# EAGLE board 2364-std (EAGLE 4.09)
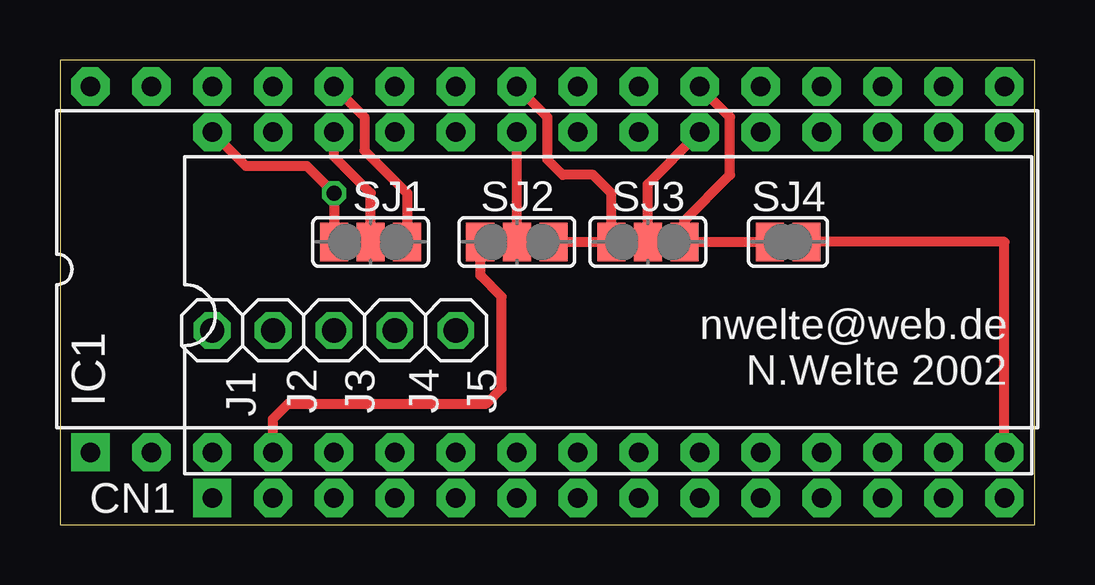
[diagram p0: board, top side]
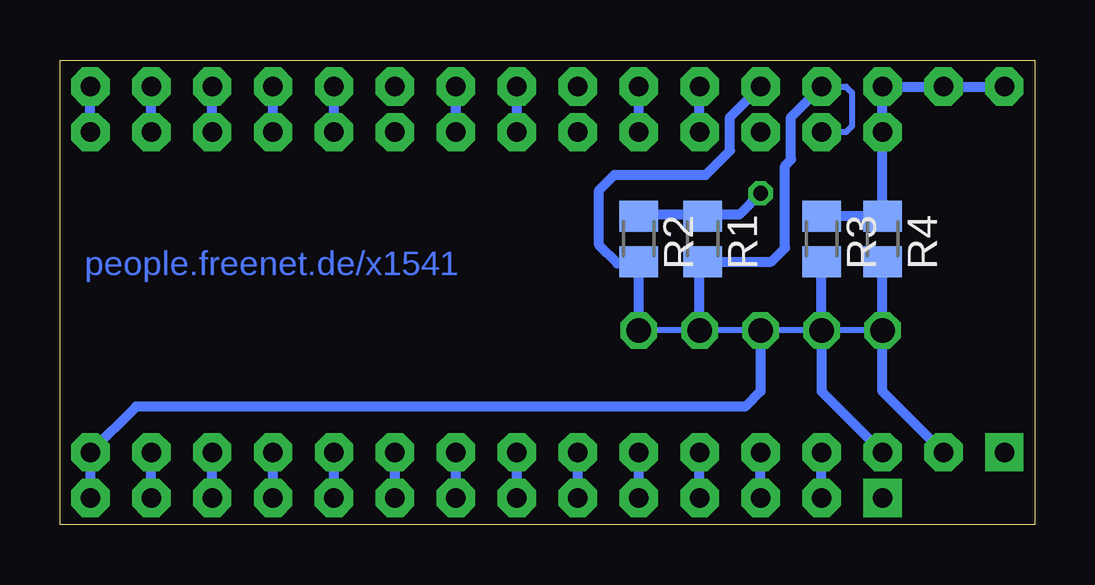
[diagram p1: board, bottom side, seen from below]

Size 40.63 x 19.36 mm. Coordinates in mm from the lower left corner, seen from the top.
Outline: 40.63,0 40.63,19.36 0,19.36 0,0 40.63,0
Copper layers used: Top, Bottom

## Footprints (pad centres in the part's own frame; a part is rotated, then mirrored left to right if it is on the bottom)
DIL28-6 = drill 0.813 pad 1.6 square: 1 -16.51,-7.62 | drill 0.813 pad 1.6 octagon: 2 -13.97,-7.62; 3 -11.43,-7.62; 4 -8.89,-7.62; 5 -6.35,-7.62; 6 -3.81,-7.62; 7 -1.27,-7.62; 8 1.27,-7.62; 9 3.81,-7.62; 10 6.35,-7.62; 11 8.89,-7.62; 12 11.43,-7.62; 13 13.97,-7.62; 14 16.51,-7.62; 15 16.51,7.62; 16 13.97,7.62; 17 11.43,7.62; 18 8.89,7.62; 19 6.35,7.62; 20 3.81,7.62; 21 1.27,7.62; 22 -1.27,7.62; 23 -3.81,7.62; 24 -6.35,7.62; 25 -8.89,7.62; 26 -11.43,7.62; 27 -13.97,7.62; 28 -16.51,7.62
DIL32-3 = drill 0.813 pad 1.6 square: 1 -19.05,-3.81 | drill 0.813 pad 1.6 octagon: 2 -16.51,-3.81; 3 -13.97,-3.81; 4 -11.43,-3.81; 5 -8.89,-3.81; 6 -6.35,-3.81; 7 -3.81,-3.81; 8 -1.27,-3.81; 9 1.27,-3.81; 10 3.81,-3.81; 11 6.35,-3.81; 12 8.89,-3.81; 13 11.43,-3.81; 14 13.97,-3.81; 15 16.51,-3.81; 16 19.05,-3.81; 17 19.05,11.43; 18 16.51,11.43; 19 13.97,11.43; 20 11.43,11.43; 21 8.89,11.43; 22 6.35,11.43; 23 3.81,11.43; 24 1.27,11.43; 25 -1.27,11.43; 26 -3.81,11.43; 27 -6.35,11.43; 28 -8.89,11.43; 29 -11.43,11.43; 30 -13.97,11.43; 31 -16.51,11.43; 32 -19.05,11.43
1X01 = drill 1.016 octagon: 1 0,0
M0805 = smd 1.3 x 1.6: 1 -0.95,0; 2 0.95,0
SJ_2 = smd 1.168 x 1.6: 1 -1.524,0; 2 0,0; 3 1.524,0
SJ = smd 1.168 x 1.6: 1 -0.762,0; 2 0.762,0

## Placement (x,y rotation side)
CN1  [DIL28-6]  22.85,8.72 0 top
IC1  AT29C010  [DIL32-3]  20.31,6.82 0 top
J1  [1X01]  8.88,8.09 90 top
J2  [1X01]  6.35,8.09 90 top
J3  [1X01]  11.43,8.09 90 top
J4  [1X01]  13.96,8.09 90 top
J5  [1X01]  16.5,8.09 90 top
R1  [M0805]  13.84,11.9 270 bottom
R2  [M0805]  16.5,11.9 270 bottom
R3  [M0805]  8.88,11.9 270 bottom
R4  [M0805]  6.35,11.9 270 bottom
SJ1  [SJ_2]  12.95,11.77 0 top
SJ2  [SJ_2]  19.04,11.77 0 top
SJ3  [SJ_2]  24.51,11.77 0 top
SJ4  [SJ]  30.35,11.77 0 top

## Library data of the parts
CN1 = memory-hitachi
IC1 = am29-memory
J1-J5 = pinhead
R1-R4 = rcl
SJ1-SJ4 = jumper

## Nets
A0: CN1.10 IC1.12
A1: CN1.9 IC1.11
A2: CN1.8 IC1.10
A3: CN1.7 IC1.9
A4: CN1.6 IC1.8
A5: CN1.5 IC1.7
A6: CN1.4 IC1.6
A7: CN1.3 IC1.5
A8: CN1.25 IC1.27
A9: CN1.24 IC1.26
A10: CN1.21 IC1.23
A11: CN1.20 IC1.25 SJ2.3 SJ3.1 SJ3.2
A12: CN1.2 CN1.23 IC1.4 SJ2.1 SJ2.2
A13: CN1.14 CN1.27 IC1.2 IC1.3 IC1.16 IC1.22 IC1.28 IC1.29 J1.1 J2.1 J3.1 J4.1 J5.1 R1.2 R2.2 R3.2 R4.2 SJ1.3 SJ3.3 SJ4.1 SJ4.2
D0: CN1.11 IC1.13
D1: CN1.12 IC1.14
D2: CN1.13 IC1.15
D3: CN1.15 IC1.17
D4: CN1.16 IC1.18
D5: CN1.17 IC1.19
D6: CN1.18 IC1.20
D7: CN1.19 IC1.21
OE: CN1.22 IC1.24
VCC: CN1.26 CN1.28 IC1.30 IC1.31 IC1.32 R1.1 R2.1 R3.1 R4.1 SJ1.1 SJ1.2

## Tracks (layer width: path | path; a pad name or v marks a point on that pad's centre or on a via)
A0
  Bottom 0.406: CN1.10 IC1.12
A1
  Bottom 0.406: CN1.9 IC1.11
A2
  Bottom 0.406: CN1.8 IC1.10
A3
  Bottom 0.406: CN1.7 IC1.9
A4
  Bottom 0.406: CN1.6 IC1.8
A5
  Bottom 0.406: CN1.5 IC1.7
A6
  Bottom 0.406: CN1.4 IC1.6
A7
  Bottom 0.406: CN1.3 IC1.5
A8
  Bottom 0.406: CN1.25 IC1.27
A9
  Bottom 0.406: CN1.24 IC1.26
A10
  Bottom 0.406: CN1.21 IC1.23
A11
  Top 0.254: SJ3.1 SJ3.2
  Top 0.406: SJ2.3 SJ3.1 22.98,13.8 22.22,14.57 20.95,14.57 20.31,15.2 20.31,16.98 IC1.25 | SJ3.2 24.51,14.19 CN1.20
A12
  Top 0.254: SJ2.1 SJ2.2
  Top 0.406: SJ2.1 17.52,10.38 18.41,9.49 18.41,5.68 17.77,5.04 9.52,5.04 8.88,4.41 IC1.4 | SJ2.2 CN1.23
  Bottom 0.406: CN1.2 IC1.4
A13
  Top 0.254: SJ4.1 SJ4.2
  Top 0.406: SJ1.3 14.47,13.8 12.7,15.58 12.7,16.98 IC1.28 | SJ4.2 39.37,11.77 IC1.16 | IC1.22 27.93,16.98 27.93,14.57 26.03,12.66 SJ3.3 SJ4.1
  Bottom 0.254: CN1.27 7.87,16.34 7.62,16.6 7.62,18 7.87,18.25 IC1.29 | 9.01,8.09 J3.1 J4.1 J5.1 | J2.1 J1.1
  Bottom 0.406: 16.5,11.01 R2.2 16.5,10.88 | J5.1 16.5,10.88 | IC1.28 12.7,16.98 12.7,15.58 13.71,14.57 17.52,14.57 18.16,13.93 18.16,11.65 17.39,10.88 16.5,10.88 | R1.2 13.84,11.01 | J4.1 13.96,10.95 R1.2 | R1.2 10.98,10.95 10.41,11.52 10.41,14.95 10.16,15.2 10.16,16.98 IC1.29 | J3.1 11.43,5.55 12.06,4.92 37.46,4.92 IC1.16 CN1.14 | J2.1 R4.2 J2.1 | IC1.2 6.35,5.55 J2.1 | 8.88,8.22 R3.2 | IC1.3 8.88,5.55 J1.1 8.88,8.22 | 8.88,8.22 9.01,8.09
D0
  Bottom 0.406: CN1.11 IC1.13
D1
  Bottom 0.406: CN1.12 IC1.14
D2
  Bottom 0.406: CN1.13 IC1.15
D3
  Bottom 0.406: CN1.15 IC1.17
D4
  Bottom 0.406: CN1.16 IC1.18
D5
  Bottom 0.406: CN1.17 IC1.19
D6
  Bottom 0.406: CN1.18 IC1.20
D7
  Bottom 0.406: CN1.19 IC1.21
OE
  Bottom 0.406: CN1.22 IC1.24
VCC  (via drill 0.61)
  Top 0.254: SJ1.1 SJ1.2
  Top 0.406: SJ1.1 v11.43,13.8 10.28,14.95 7.74,14.95 CN1.28 | SJ1.2 12.95,13.8 11.43,15.33 CN1.26
  Bottom 0.406: IC1.32 IC1.31 IC1.30 CN1.28 6.35,12.92 | R4.1 6.35,12.92 | 6.35,12.92 6.41,12.85 R3.1 8.88,12.79 | 13.84,12.79 R1.1 13.84,12.92 | R2.1 16.5,12.92 13.84,12.92 | v11.43,13.8 12.31,12.92 13.84,12.92

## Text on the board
Bottom: people.freenet.de/x1541
tNames: nwelte@web.de | N.Welte 2002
